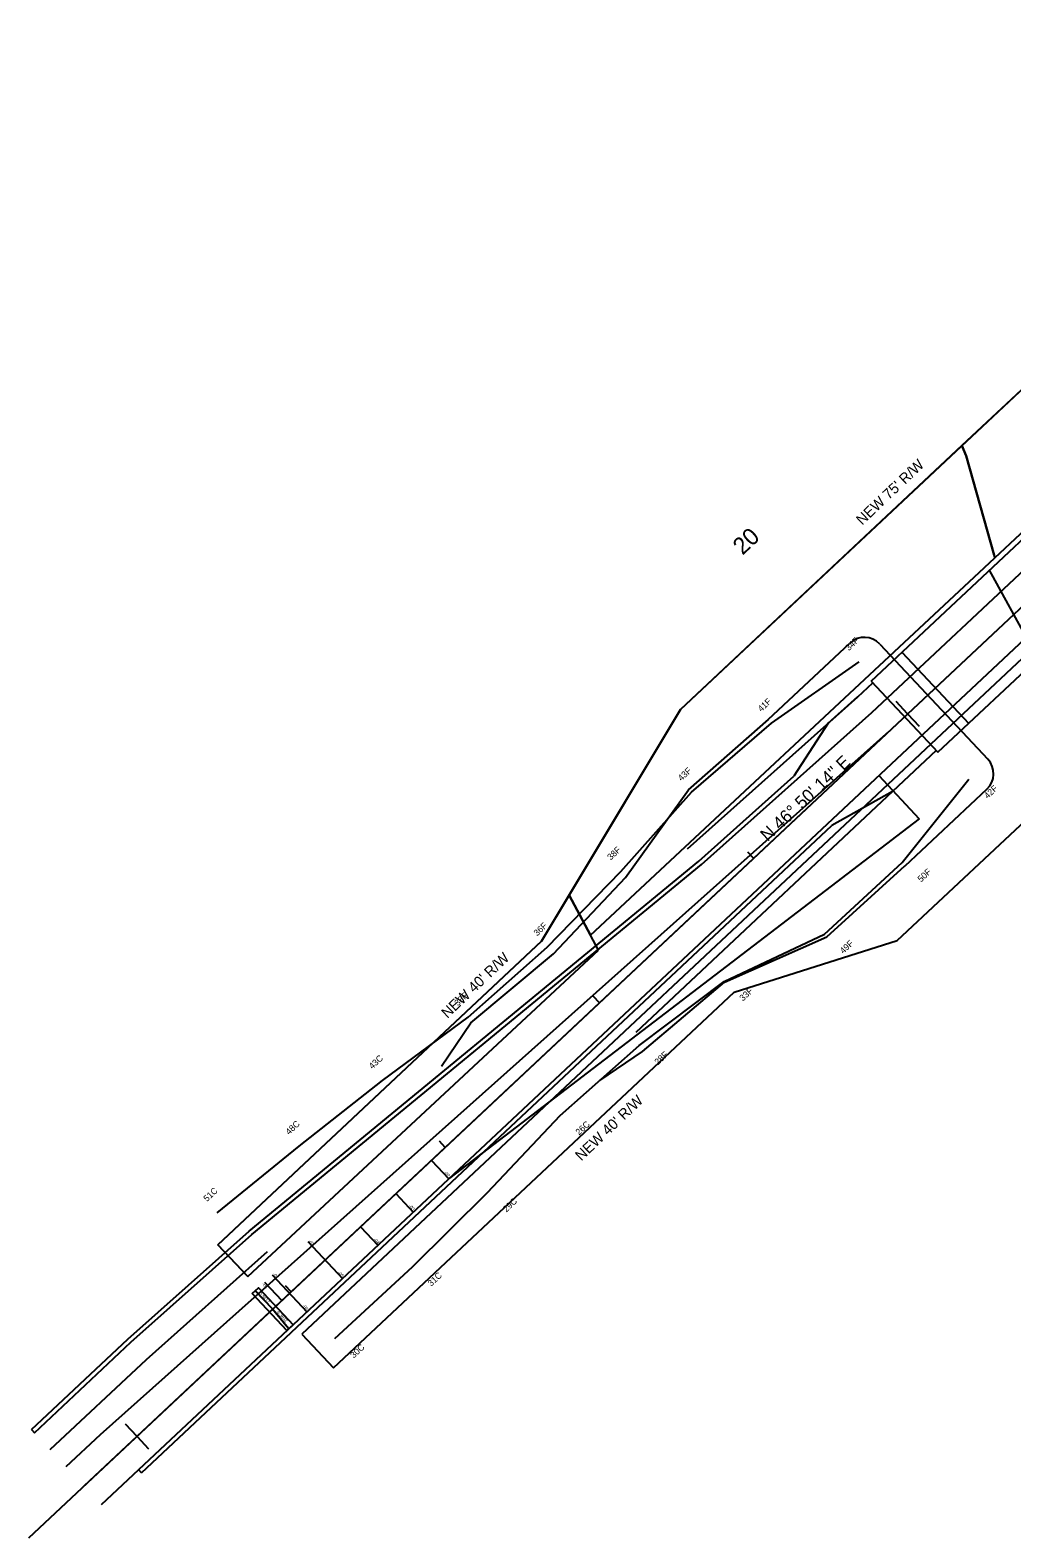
# Model space of a CAD drawing. Extents: x 1623239 to 1625698, y 1118659 to 1120751.
# Drawn here: x 1623938 to 1624403, y 1119210 to 1119923 of the extents above; entities that cross this region are included whole.
import ezdxf

# ---------------------------------------------------------------- set-up
doc = ezdxf.new("R2010")
doc.units = 0
for name, color, linetype in [('BR_CONCRETE', 7, 'Continuous'), ('Default', 7, 'Continuous'), ('RD_HC_Cl', 7, 'Continuous'), ('RD_HC_Data', 7, 'Continuous'), ('RD_HC_Data_Tic', 7, 'Continuous'), ('RD_HC_TX_Sta50', 7, 'Continuous'), ('RD_PD_ALT1_TX', 7, 'Continuous'), ('RD_PD_CstnLmt', 7, 'Continuous'), ('RD_PD_CstnLmt_TX', 7, 'Continuous'), ('RD_PD_DR_ErosCtrl', 7, 'Continuous'), ('RD_PD_GR', 7, 'Continuous'), ('RD_PD_PaintMed', 7, 'Continuous'), ('RD_PD_PaveShd', 7, 'Continuous'), ('RD_PD_RW', 7, 'Continuous'), ('RD_PD_RW_TX', 7, 'Continuous'), ('RD_QTY_Clear_Grub', 7, 'Continuous'), ('RD_Sketch8', 7, 'Continuous'), ('RD_TX_Pipe_ElevEX', 7, 'Continuous')]:
    doc.layers.add(name, color=color, linetype=linetype)

msp = doc.modelspace()

# ---------------------------------------------------------------- linework, layer by layer
at = {"layer": 'BR_CONCRETE'}
for p, q in [((1624335.9, 1119615.36), (1624438.01, 1119711.13)), ((1624367.53, 1119581.63), (1624469.65, 1119677.4)), ((1624350.48, 1119629.04), (1624382.12, 1119595.31)), ((1624335.9, 1119615.36), (1624367.53, 1119581.63))]:
    msp.add_line(p, q, dxfattribs=at)
at = {"layer": 'Default'}
msp.add_lwpolyline([(1624391.81, 1119667.8), (1624411.15, 1119632.51), (1624414.74, 1119625.9)], dxfattribs=at)
at = {"layer": 'RD_HC_Cl'}
msp.add_line((1623937.25, 1119209.79), (1624678.65, 1119905.11), dxfattribs=at)
msp.add_line((1623937.25, 1119209.79), (1624678.65, 1119905.11), dxfattribs=at)
at = {"layer": 'RD_HC_Data_Tic'}
for p, q in [((1624353.17, 1119599.86), (1624347.7, 1119605.7)), ((1624353.17, 1119599.86), (1624358.65, 1119594.03)), ((1624280.23, 1119531.46), (1624277.5, 1119534.37)), ((1624207.29, 1119463.05), (1624204.55, 1119465.97)), ((1624134.35, 1119394.64), (1624131.61, 1119397.56)), ((1624061.41, 1119326.23), (1624058.67, 1119329.15)), ((1623988.47, 1119257.83), (1623982.99, 1119263.66)), ((1623988.47, 1119257.83), (1623993.94, 1119251.99))]:
    msp.add_line(p, q, dxfattribs=at)
at = {"layer": 'RD_PD_ALT1_TX'}
for p, q in [((1624127.78, 1119388.49), (1624135.99, 1119379.73)), ((1624111.01, 1119372.75), (1624119.22, 1119364)), ((1624094.23, 1119357.02), (1624102.44, 1119348.27)), ((1624069.25, 1119350.04), (1624085.66, 1119332.53)), ((1624052.47, 1119334.3), (1624068.89, 1119316.8))]:
    msp.add_line(p, q, dxfattribs=at)
at = {"layer": 'RD_PD_CstnLmt'}
for p, q in [((1624288.73, 1119595.49), (1624330.19, 1119624.38)), ((1624250.91, 1119562.72), (1624288.73, 1119595.49)), ((1624350.67, 1119529.44), (1624382.16, 1119568.96)), ((1624217.48, 1119525.28), (1624250.91, 1119562.72)), ((1624182.63, 1119489.34), (1624217.48, 1119525.28)), ((1624313.88, 1119495.57), (1624350.67, 1119529.44)), ((1624266.38, 1119473.13), (1624313.88, 1119495.57)), ((1624145.13, 1119456.24), (1624182.63, 1119489.34)), ((1624226.17, 1119442.92), (1624266.38, 1119473.13)), ((1624104.63, 1119426.33), (1624145.13, 1119456.24)), ((1624188.81, 1119409.67), (1624226.17, 1119442.92)), ((1624065.22, 1119395.26), (1624104.63, 1119426.33)), ((1624154.41, 1119373.25), (1624188.81, 1119409.67)), ((1624026.36, 1119363.61), (1624065.22, 1119395.26)), ((1624118.81, 1119338.12), (1624154.41, 1119373.25)), ((1624082.16, 1119304.1), (1624118.81, 1119338.12))]:
    msp.add_line(p, q, dxfattribs=at)
at = {"layer": 'RD_PD_DR_ErosCtrl'}
for p, q in [((1624287.23, 1119597.09), (1624325.89, 1119633.35)), ((1624340.02, 1119632.89), (1624391.16, 1119578.36)), ((1624249.45, 1119563.92), (1624287.3, 1119597.16)), ((1624219.66, 1119522.39), (1624249.45, 1119563.92)), ((1624352.05, 1119527.97), (1624390.71, 1119564.22)), ((1624314.87, 1119494.22), (1624351.9, 1119527.82)), ((1624185.55, 1119486.22), (1624219.66, 1119522.39)), ((1624266.46, 1119472.83), (1624314.87, 1119494.22)), ((1624146.45, 1119453.56), (1624185.55, 1119486.22)), ((1624227.74, 1119440.02), (1624266.46, 1119472.83)), ((1624132.64, 1119433.02), (1624146.45, 1119453.56)), ((1624207.55, 1119426.23), (1624227.74, 1119440.02))]:
    msp.add_line(p, q, dxfattribs=at)
for centre, start, end in [((1624332.73, 1119626.05), 43.16267, 133.16267), ((1624383.87, 1119571.52), 313.16267, 43.16267)]:
    msp.add_arc(centre, 10, start, end, dxfattribs=at)
at = {"layer": 'RD_PD_GR'}
for p, q in [((1624329.57, 1119607.89), (1624336.67, 1119614.54)), ((1624248.98, 1119536.01), (1624329.57, 1119607.89)), ((1624366.76, 1119582.45), (1624224.53, 1119449.05))]:
    msp.add_line(p, q, dxfattribs=at)
at = {"layer": 'RD_PD_PaintMed'}
for p, q in [((1623963.49, 1119234.4), (1624678.65, 1119905.11)), ((1623971.7, 1119225.65), (1624686.87, 1119896.36)), ((1624336.32, 1119600.51), (1624621.14, 1119867.62)), ((1624255.64, 1119528.55), (1624336.32, 1119600.51)), ((1623971.16, 1119258.74), (1624344.42, 1119591.65)), ((1624042.77, 1119353.42), (1624255.64, 1119528.55)), ((1623985.5, 1119302.34), (1624042.77, 1119353.42)), ((1623992.92, 1119294.23), (1624050.29, 1119345.39)), ((1623939.89, 1119259.57), (1623985.5, 1119302.34)), ((1623947.41, 1119251.54), (1623992.92, 1119294.23)), ((1623954.94, 1119243.52), (1623971.16, 1119258.74))]:
    msp.add_line(p, q, dxfattribs=at)
at = {"layer": 'RD_PD_PaveShd'}
for p, q in [((1624315.65, 1119595.47), (1624329.67, 1119607.97)), ((1624315.65, 1119595.47), (1624299.4, 1119570.26)), ((1624366.76, 1119582.45), (1624346.06, 1119563.03)), ((1624254.3, 1119530.04), (1624299.4, 1119570.26)), ((1624346.06, 1119563.03), (1624317.24, 1119546.97)), ((1623990.57, 1119240.61), (1624317.24, 1119546.97)), ((1624041.5, 1119354.97), (1624254.37, 1119530.09)), ((1623984.17, 1119303.84), (1624041.47, 1119354.95)), ((1623938.52, 1119261.03), (1623984.13, 1119303.8)), ((1623938.52, 1119261.03), (1623939.89, 1119259.57)), ((1623990.57, 1119240.61), (1623989.2, 1119242.07))]:
    msp.add_line(p, q, dxfattribs=at)
at = {"layer": 'RD_PD_RW'}
for p, q in [((1624245.7, 1119601.9), (1624457.23, 1119800.28)), ((1624348.31, 1119492.48), (1624559.84, 1119690.86)), ((1624179.93, 1119492.23), (1624245.7, 1119601.9)), ((1624026.75, 1119348.57), (1624179.93, 1119492.23)), ((1624271.12, 1119468.08), (1624348.31, 1119492.48)), ((1624081.48, 1119290.22), (1624271.12, 1119468.08)), ((1624040.88, 1119333.5), (1624026.75, 1119348.57)), ((1624066.43, 1119306.26), (1624081.48, 1119290.22))]:
    msp.add_line(p, q, dxfattribs=at)
at = {"layer": 'RD_QTY_Clear_Grub'}
for p, q in [((1624394.42, 1119673.64), (1624660.93, 1119923.47)), ((1624457.23, 1119800.28), (1624378.88, 1119726.79)), ((1624378.88, 1119726.79), (1624245.7, 1119601.9)), ((1624380.9, 1119721.92), (1624378.88, 1119726.79)), ((1624378.88, 1119726.79), (1624380.9, 1119721.92)), ((1624394.13, 1119674.93), (1624380.9, 1119721.92)), ((1624380.9, 1119721.92), (1624394.13, 1119674.93)), ((1624384.7, 1119664.53), (1624394.42, 1119673.64)), ((1624394.42, 1119673.64), (1624394.13, 1119674.93)), ((1624394.13, 1119674.93), (1624394.42, 1119673.64)), ((1624203.06, 1119495.09), (1624384.7, 1119664.53)), ((1624409.91, 1119628.39), (1624066.43, 1119306.26)), ((1624245.7, 1119601.9), (1624192.99, 1119514.01)), ((1624348.31, 1119492.48), (1624438.51, 1119577.07)), ((1624192.99, 1119514.01), (1624179.93, 1119492.23)), ((1624203.06, 1119495.09), (1624192.99, 1119514.01)), ((1624192.99, 1119514.01), (1624203.06, 1119495.09)), ((1624206.88, 1119487.91), (1624203.06, 1119495.09)), ((1624179.93, 1119492.23), (1624026.75, 1119348.57)), ((1624040.88, 1119333.5), (1624206.88, 1119487.91)), ((1624271.12, 1119468.08), (1624348.31, 1119492.48)), ((1624081.48, 1119290.22), (1624271.12, 1119468.08)), ((1624026.75, 1119348.57), (1624040.88, 1119333.5)), ((1624066.43, 1119306.26), (1624081.48, 1119290.22))]:
    msp.add_line(p, q, dxfattribs=at)
at = {"layer": 'RD_Sketch8'}
for p, q in [((1624339.5, 1119570.59), (1624358.65, 1119550.16)), ((1624358.65, 1119550.16), (1624136.29, 1119380.01))]:
    msp.add_line(p, q, dxfattribs=at)
at = {"layer": 'RD_TX_Pipe_ElevEX'}
for p, q in [((1624048.82, 1119330.88), (1624057.03, 1119322.13)), ((1624052.69, 1119318.06), (1624044.41, 1119326.75)), ((1624052.69, 1119318.06), (1624060.08, 1119309.1))]:
    msp.add_line(p, q, dxfattribs=at)
msp.add_lwpolyline([(1624042.99, 1119325.41), (1624045.9, 1119328.15), (1624062.32, 1119310.64), (1624059.41, 1119307.9)], close=True, dxfattribs=at)
msp.add_lwpolyline([(1624044.41, 1119326.75), (1624044.47, 1119326.68), (1624051.46, 1119319.37), (1624052.64, 1119318.12), (1624059.09, 1119310.32), (1624060.08, 1119309.1), (1624060.3, 1119308.74)], dxfattribs=at)

# ---------------------------------------------------------------- texts
at = {"layer": 'RD_HC_Data'}
msp.add_text('N 46%%d 50\' 14" E', height=6, rotation=43.16267, dxfattribs=at).set_placement((1624286.92, 1119539.1))
at = {"layer": 'RD_HC_TX_Sta50'}
msp.add_text('20', height=8, rotation=43.16267, dxfattribs=at).set_placement((1624275.07, 1119674.68))
at = {"layer": 'RD_PD_ALT1_TX'}
for s, p in [('-02', (1624133.64, 1119382.51)), ('-03', (1624116.92, 1119366.72)), ('-02', (1624069.37, 1119350.06)), ('-04', (1624100.3, 1119350.85)), ('-01', (1624052.52, 1119334.48)), ('-05', (1624083.36, 1119335.14)), ('-06', (1624066.57, 1119319.49))]:
    msp.add_text(s, height=1.5, rotation=313.16267, dxfattribs=at).set_placement(p)
at = {"layer": 'RD_PD_CstnLmt_TX'}
for s, p in [('34F', (1624325.4, 1119629.48)), ('41F', (1624283.94, 1119600.59)), ('43F', (1624246.12, 1119567.83)), ('42F', (1624391.05, 1119559.47)), ('38F', (1624212.69, 1119530.38)), ('50F', (1624359.57, 1119519.96)), ('36F', (1624177.85, 1119494.45)), ('49F', (1624322.78, 1119486.09)), ('38F', (1624140.34, 1119461.34)), ('33F', (1624275.27, 1119463.65)), ('43C', (1624099.84, 1119431.44)), ('28F', (1624235.06, 1119433.44)), ('48C', (1624060.44, 1119400.36)), ('26C', (1624197.7, 1119400.18)), ('51C', (1624021.57, 1119368.72)), ('29C', (1624163.3, 1119363.77)), ('31C', (1624127.7, 1119328.64)), ('30C', (1624091.06, 1119294.62))]:
    msp.add_text(s, height=3, rotation=43.16267, dxfattribs=at).set_placement(p)
at = {"layer": 'RD_PD_RW_TX'}
for s, p in [("NEW 75' R/W", (1624331.67, 1119688.87)), ("NEW 40' R/W", (1624135.38, 1119455.44)), ("NEW 40' R/W", (1624198.71, 1119387.92))]:
    msp.add_text(s, height=5, rotation=43.605, dxfattribs=at).set_placement(p)
at = {"layer": 'RD_TX_Pipe_ElevEX'}
for s, p in [('-0.8417', (1624045.59, 1119325.81)), ('-01', (1624047.53, 1119329.8)), ('-6.3832', (1624054.06, 1119316.83))]:
    msp.add_text(s, height=1.5, rotation=313.16267, dxfattribs=at).set_placement(p)

doc.saveas('drawing.dxf')
